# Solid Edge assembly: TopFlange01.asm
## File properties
Author: ptcarter
Template: Normal.asm
Last saved by: ptcarter
Revision: 21
Application: Solid Edge
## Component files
TopFlange.par
ScrewM8.par
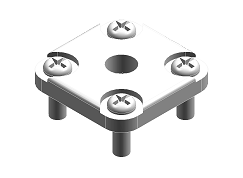
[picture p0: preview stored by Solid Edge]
